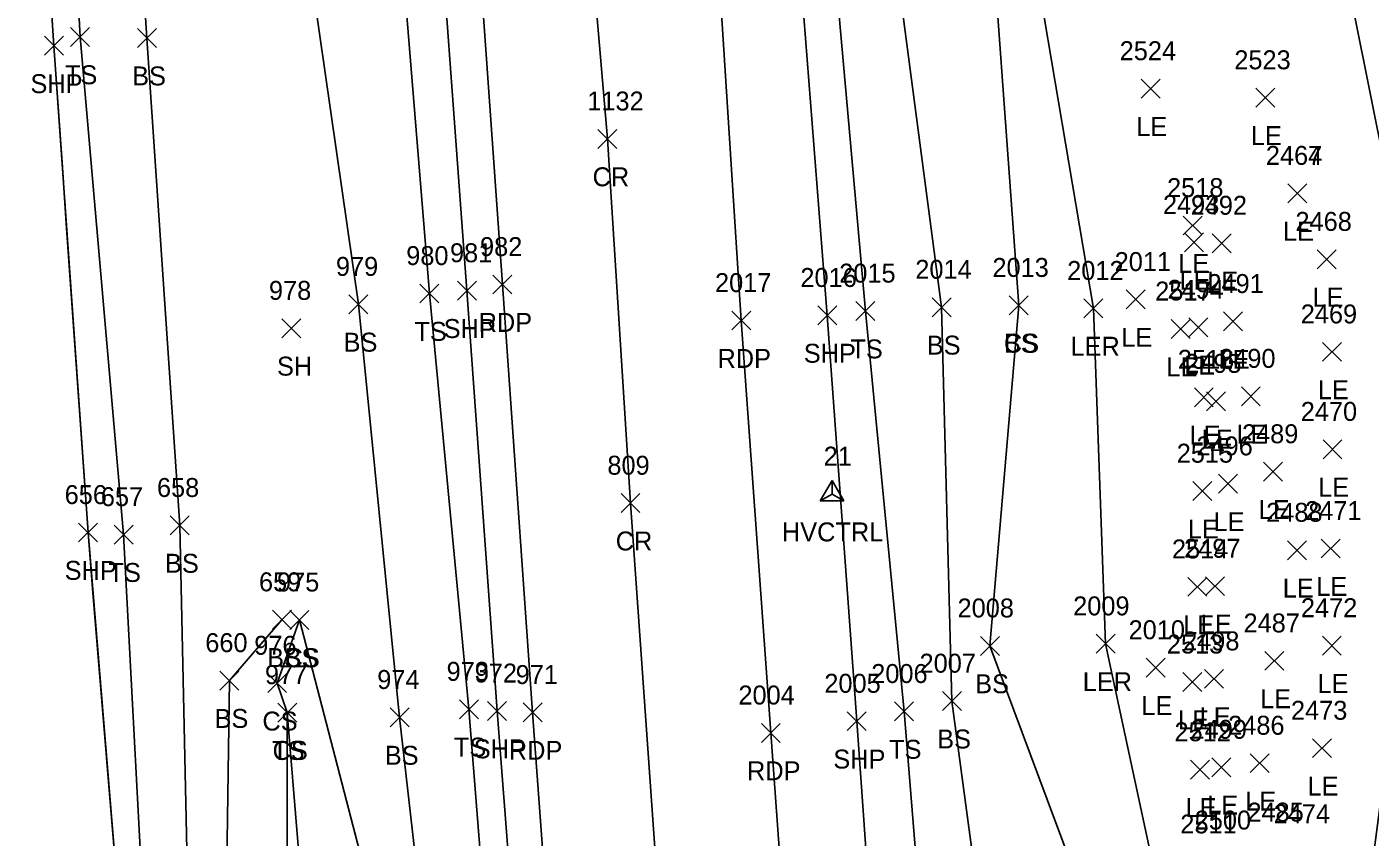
# Model space of a CAD drawing. Extents: x 1650221 to 1650634, y 244606 to 249996.
# Drawn here: x 1650345.8 to 1650487.6, y 245576.1 to 245661.6 of the extents above; entities that cross this region are included whole.
import ezdxf

# ---------------------------------------------------------------- set-up
doc = ezdxf.new("R2010")
doc.units = 0
for name, color, linetype in [('C_A', 7, 'Continuous'), ('C_I', 7, 'Continuous'), ('CPSM', 7, 'Continuous'), ('L_A', 7, 'Continuous'), ('L_I', 7, 'Continuous'), ('L_TIC', 7, 'Continuous'), ('LARO', 7, 'Continuous'), ('LELB', 7, 'Continuous'), ('LSOGP', 7, 'Continuous'), ('P_A', 7, 'Continuous'), ('P_I', 7, 'Continuous'), ('P_TIC', 7, 'Continuous'), ('PET', 7, 'Continuous'), ('PRC', 7, 'Continuous'), ('PSP', 7, 'Continuous')]:
    doc.layers.add(name, color=color, linetype=linetype)

msp = doc.modelspace()

# ---------------------------------------------------------------- linework, layer by layer
at = {"layer": 'CPSM'}
for p, q in [((1650429.52, 245611.6), (1650430.77, 245613.77)), ((1650432.02, 245611.6), (1650430.77, 245613.77)), ((1650430.77, 245612.33), (1650430.77, 245613.77)), ((1650429.52, 245611.6), (1650430.77, 245612.33)), ((1650430.77, 245612.33), (1650430.77, 245612.33)), ((1650430.77, 245612.33), (1650432.02, 245611.6)), ((1650429.52, 245611.6), (1650432.02, 245611.6))]:
    msp.add_line(p, q, dxfattribs=at)
at = {"layer": 'L_TIC'}
for points in [[(1650350.39, 245659.59), (1650352.39, 245661.59)], [(1650352.39, 245659.59), (1650350.39, 245661.59)], [(1650357.45, 245659.47), (1650359.45, 245661.47)], [(1650359.45, 245659.47), (1650357.45, 245661.47)], [(1650463.38, 245654.13), (1650465.38, 245656.13)], [(1650465.38, 245654.13), (1650463.38, 245656.13)], [(1650475.48, 245653.17), (1650477.48, 245655.17)], [(1650477.48, 245653.17), (1650475.48, 245655.17)], [(1650478.86, 245643.08), (1650480.86, 245645.08)], [(1650480.86, 245643.08), (1650478.86, 245645.08)], [(1650478.86, 245643.08), (1650480.86, 245645.08)], [(1650480.86, 245643.08), (1650478.86, 245645.08)], [(1650467.81, 245639.68), (1650469.81, 245641.68)], [(1650469.81, 245639.68), (1650467.81, 245641.68)], [(1650467.95, 245637.89), (1650469.95, 245639.89)], [(1650469.95, 245637.89), (1650467.95, 245639.89)], [(1650470.87, 245637.81), (1650472.87, 245639.81)], [(1650472.87, 245637.81), (1650470.87, 245639.81)], [(1650481.98, 245636.11), (1650483.98, 245638.11)], [(1650483.98, 245636.11), (1650481.98, 245638.11)], [(1650379.77, 245631.36), (1650381.77, 245633.36)], [(1650381.77, 245631.36), (1650379.77, 245633.36)], [(1650387.27, 245632.5), (1650389.27, 245634.5)], [(1650389.27, 245632.5), (1650387.27, 245634.5)], [(1650449.46, 245631.25), (1650451.46, 245633.25)], [(1650451.46, 245631.25), (1650449.46, 245633.25)], [(1650449.46, 245631.25), (1650451.46, 245633.25)], [(1650451.46, 245631.25), (1650449.46, 245633.25)], [(1650461.8, 245631.87), (1650463.8, 245633.87)], [(1650463.8, 245631.87), (1650461.8, 245633.87)], [(1650433.29, 245630.65), (1650435.29, 245632.65)], [(1650435.29, 245630.65), (1650433.29, 245632.65)], [(1650441.32, 245631.05), (1650443.32, 245633.05)], [(1650443.32, 245631.05), (1650441.32, 245633.05)], [(1650457.35, 245630.93), (1650459.35, 245632.93)], [(1650459.35, 245630.93), (1650457.35, 245632.93)], [(1650372.69, 245628.83), (1650374.69, 245630.83)], [(1650374.69, 245628.83), (1650372.69, 245630.83)], [(1650466.56, 245628.76), (1650468.56, 245630.76)], [(1650468.56, 245628.76), (1650466.56, 245630.76)], [(1650468.43, 245628.94), (1650470.43, 245630.94)], [(1650470.43, 245628.94), (1650468.43, 245630.94)], [(1650472.07, 245629.55), (1650474.07, 245631.55)], [(1650474.07, 245629.55), (1650472.07, 245631.55)], [(1650482.54, 245626.34), (1650484.54, 245628.34)], [(1650484.54, 245626.34), (1650482.54, 245628.34)], [(1650469, 245621.55), (1650471, 245623.55)], [(1650471, 245621.55), (1650469, 245623.55)], [(1650473.96, 245621.65), (1650475.96, 245623.65)], [(1650475.96, 245621.65), (1650473.96, 245623.65)], [(1650470.29, 245621.12), (1650472.29, 245623.12)], [(1650472.29, 245621.12), (1650470.29, 245623.12)], [(1650482.58, 245616.05), (1650484.58, 245618.05)], [(1650484.58, 245616.05), (1650482.58, 245618.05)], [(1650476.3, 245613.69), (1650478.3, 245615.69)], [(1650478.3, 245613.69), (1650476.3, 245615.69)], [(1650468.83, 245611.64), (1650470.83, 245613.64)], [(1650470.83, 245611.64), (1650468.83, 245613.64)], [(1650471.54, 245612.41), (1650473.54, 245614.41)], [(1650473.54, 245612.41), (1650471.54, 245614.41)], [(1650354.99, 245607.05), (1650356.99, 245609.05)], [(1650356.99, 245607.05), (1650354.99, 245609.05)], [(1650360.92, 245608.02), (1650362.92, 245610.02)], [(1650362.92, 245608.02), (1650360.92, 245610.02)], [(1650478.84, 245605.4), (1650480.84, 245607.4)], [(1650480.84, 245605.4), (1650478.84, 245607.4)], [(1650482.38, 245605.58), (1650484.38, 245607.58)], [(1650484.38, 245605.58), (1650482.38, 245607.58)], [(1650468.33, 245601.53), (1650470.33, 245603.53)], [(1650470.33, 245601.53), (1650468.33, 245603.53)], [(1650470.18, 245601.6), (1650472.18, 245603.6)], [(1650472.18, 245601.6), (1650470.18, 245603.6)], [(1650371.7, 245598.06), (1650373.7, 245600.06)], [(1650373.7, 245598.06), (1650371.7, 245600.06)], [(1650373.54, 245598.04), (1650375.54, 245600.04)], [(1650375.54, 245598.04), (1650373.54, 245600.04)], [(1650373.54, 245598.04), (1650375.54, 245600.04)], [(1650375.54, 245598.04), (1650373.54, 245600.04)], [(1650446.43, 245595.3), (1650448.43, 245597.3)], [(1650448.43, 245595.3), (1650446.43, 245597.3)], [(1650458.64, 245595.52), (1650460.64, 245597.52)], [(1650460.64, 245595.52), (1650458.64, 245597.52)], [(1650482.51, 245595.33), (1650484.51, 245597.33)], [(1650484.51, 245595.33), (1650482.51, 245597.33)], [(1650463.92, 245593), (1650465.92, 245595)], [(1650465.92, 245593), (1650463.92, 245595)], [(1650476.45, 245593.72), (1650478.45, 245595.72)], [(1650478.45, 245593.72), (1650476.45, 245595.72)], [(1650366.15, 245591.64), (1650368.15, 245593.64)], [(1650368.15, 245591.64), (1650366.15, 245593.64)], [(1650467.79, 245591.49), (1650469.79, 245593.49)], [(1650469.79, 245591.49), (1650467.79, 245593.49)], [(1650470.07, 245591.82), (1650472.07, 245593.82)], [(1650472.07, 245591.82), (1650470.07, 245593.82)], [(1650371.2, 245591.36), (1650373.2, 245593.36)], [(1650373.2, 245591.36), (1650371.2, 245593.36)], [(1650391.44, 245588.61), (1650393.44, 245590.61)], [(1650393.44, 245588.61), (1650391.44, 245590.61)], [(1650442.42, 245589.47), (1650444.42, 245591.47)], [(1650444.42, 245589.47), (1650442.42, 245591.47)], [(1650372.27, 245588.26), (1650374.27, 245590.26)], [(1650374.27, 245588.26), (1650372.27, 245590.26)], [(1650372.27, 245588.26), (1650374.27, 245590.26)], [(1650374.27, 245588.26), (1650372.27, 245590.26)], [(1650372.27, 245588.26), (1650374.27, 245590.26)], [(1650374.27, 245588.26), (1650372.27, 245590.26)], [(1650384.12, 245587.75), (1650386.12, 245589.75)], [(1650386.12, 245587.75), (1650384.12, 245589.75)], [(1650437.37, 245588.38), (1650439.37, 245590.38)], [(1650439.37, 245588.38), (1650437.37, 245590.38)], [(1650481.46, 245584.5), (1650483.46, 245586.5)], [(1650483.46, 245584.5), (1650481.46, 245586.5)], [(1650474.88, 245582.92), (1650476.88, 245584.92)], [(1650476.88, 245582.92), (1650474.88, 245584.92)], [(1650468.59, 245582.23), (1650470.59, 245584.23)], [(1650470.59, 245582.23), (1650468.59, 245584.23)], [(1650470.86, 245582.49), (1650472.86, 245584.49)], [(1650472.86, 245582.49), (1650470.86, 245584.49)]]:
    msp.add_lwpolyline(points, dxfattribs=at)
at = {"layer": 'LARO'}
msp.add_lwpolyline([(1650491, 245121.86), (1650493.61, 245139.73), (1650488.81, 245187.64), (1650492.44, 245198.75), (1650485.3, 245221.37), (1650479.96, 245259.68), (1650476.93, 245285.6), (1650472.44, 245315.86), (1650475.26, 245352.64), (1650477.44, 245377.75), (1650471.06, 245430.31), (1650471.03, 245462.47), (1650469.65, 245517.3), (1650470.03, 245548.03), (1650459.64, 245596.52), (1650458.35, 245631.93), (1650449.5, 245684.33)], dxfattribs=at)
at = {"layer": 'LELB'}
for points in [[(1650349.13, 245703.09), (1650351.39, 245660.59), (1650355.99, 245608.05), (1650358.47, 245560.96), (1650362.91, 245508.7), (1650365.76, 245471.06), (1650369.41, 245419.53), (1650373.04, 245367.18), (1650376.89, 245316.29), (1650379.01, 245269.77), (1650383.48, 245220.96), (1650387.1, 245168.26), (1650390.97, 245118.17), (1650394.99, 245063.19), (1650398.03, 245017.1), (1650401.94, 244967.25), (1650403.81, 244936.86), (1650407.34, 244889.23), (1650410.84, 244834.73), (1650414.52, 244785.95), (1650419.34, 244732.83), (1650422.93, 244682.99), (1650426.36, 244632.18), (1650427.51, 244611.7)], [(1650355.71, 245703.22), (1650358.45, 245660.47), (1650361.92, 245609.02), (1650362.95, 245561.76), (1650366.97, 245508.68), (1650370.97, 245471.38), (1650374.07, 245419.38), (1650376.64, 245367.03), (1650382.18, 245316.08), (1650385.68, 245270.43), (1650388.77, 245221.07), (1650390.77, 245168.69), (1650394.69, 245118), (1650401.29, 245063.19), (1650403.89, 245017.69), (1650406.99, 244966.96), (1650408.31, 244937.61), (1650413.12, 244889.16), (1650416.09, 244835.73), (1650420.51, 244786.1), (1650423.8, 244733.3), (1650426.51, 244682.57), (1650434.12, 244632.73), (1650437.01, 244612.78)], [(1650458.26, 244631.23), (1650456.79, 244671.65), (1650452.78, 244720.4), (1650448.37, 244766.08), (1650444.9, 244801.26), (1650441.62, 244837.94), (1650439.87, 244879.23), (1650437.68, 244923.9), (1650433.87, 244972.21), (1650429.49, 245017.89), (1650426.15, 245066.7), (1650422.69, 245123.12), (1650419.86, 245170.84), (1650416.52, 245219.13), (1650411.95, 245271.56), (1650407.71, 245328.35), (1650401.82, 245379.92), (1650396.45, 245433.97), (1650394.84, 245478.56), (1650392.49, 245522.5), (1650389.35, 245551.29), (1650385.12, 245588.75), (1650380.77, 245632.36), (1650373.15, 245685.41)], [(1650462.3, 244631.92), (1650459.1, 244671.43), (1650455.6, 244720.68), (1650451.8, 244765.92), (1650449.21, 244801.88), (1650446.61, 244838.72), (1650443.38, 244880.99), (1650440.04, 244922.8), (1650437.91, 244972.67), (1650433.82, 245018.12), (1650431.01, 245067.65), (1650425.84, 245123.86), (1650424.05, 245171.63), (1650419.6, 245218.92), (1650416.04, 245272.16), (1650411.76, 245328.09), (1650406.63, 245381.03), (1650402.95, 245434.27), (1650400.25, 245479.81), (1650396.41, 245522.79), (1650395.43, 245551.92), (1650392.44, 245589.61), (1650388.27, 245633.5), (1650384.04, 245685.26)], [(1650489.71, 244991.22), (1650489.69, 245009.71), (1650486.09, 245047.64), (1650483.87, 245079.25), (1650480.92, 245116.18), (1650479.42, 245140.42), (1650476.29, 245187.3), (1650474, 245221.05), (1650469.02, 245258.31), (1650465.71, 245285.05), (1650462.26, 245315.54), (1650460.48, 245356.55), (1650462.16, 245378.82), (1650455.67, 245427.55), (1650451.48, 245462.76), (1650449.79, 245512.44), (1650449.11, 245548.12), (1650443.42, 245590.47), (1650442.32, 245632.05), (1650435.43, 245684.43)], [(1650471.05, 245115.28), (1650468.74, 245140.33), (1650464.89, 245185.98), (1650463.25, 245221.34), (1650461.37, 245257.85), (1650459.32, 245284.8), (1650456.97, 245315.55), (1650454.6, 245356.59), (1650452.98, 245378.54), (1650450.43, 245426.58), (1650446.12, 245463.42), (1650443.52, 245512.09), (1650441.71, 245548.12), (1650438.37, 245589.38), (1650434.29, 245631.65), (1650429.68, 245683.37)], [(1650450.46, 245632.25), (1650446.79, 245683.08)], [(1650504.95, 245130.46), (1650502.44, 245141.72), (1650499.16, 245156.24), (1650498.93, 245181.82), (1650503.83, 245194.54), (1650500.59, 245204.36), (1650497.12, 245222.6), (1650494.12, 245240.25), (1650494.91, 245258.03), (1650492.2, 245286.73), (1650496.63, 245312.12), (1650498.98, 245327.58), (1650495.95, 245351.61), (1650501.94, 245378.34), (1650498.52, 245407), (1650497.68, 245445.99), (1650496.14, 245475.39), (1650481.11, 245501.15), (1650483.43, 245539.97), (1650491.3, 245600.05), (1650490.9, 245637.99), (1650484.15, 245671.67)], [(1650493.15, 245007.74), (1650488.13, 245047.67), (1650486.59, 245079.09), (1650485.35, 245117.44), (1650483.97, 245140), (1650485.34, 245188.31), (1650482.43, 245221.37), (1650477.25, 245258), (1650473.1, 245285.62), (1650468.47, 245315.46), (1650468.65, 245355.64), (1650472.97, 245377.88), (1650463.98, 245429.04), (1650464.45, 245462.11), (1650460.79, 245514.67), (1650465.46, 245547.92), (1650447.43, 245596.3), (1650450.46, 245632.25)], [(1650372.7, 245599.06), (1650367.15, 245592.64), (1650366.7, 245561.16), (1650370.23, 245505.43)], [(1650374.54, 245599.04), (1650372.2, 245592.36), (1650373.27, 245589.26)], [(1650417.42, 245170.71), (1650414.29, 245218.92), (1650409.59, 245271.3), (1650405.4, 245327.96), (1650399.15, 245380.06), (1650394.45, 245434.24), (1650392.17, 245479.25), (1650388.55, 245523.47), (1650387.04, 245550.93), (1650374.54, 245599.04)], [(1650411.56, 245100.31), (1650410.98, 245134.62), (1650407.62, 245167.58), (1650401.15, 245195.95), (1650400.96, 245232.6), (1650396.91, 245255.72), (1650396.39, 245280.59), (1650392.18, 245317.33), (1650390.56, 245355.55), (1650386.02, 245389.39), (1650383.37, 245430.51), (1650379.67, 245462.51), (1650379.96, 245467.43), (1650380, 245489.06), (1650377.56, 245510.96), (1650374.72, 245546.33), (1650373.24, 245560.96), (1650373.27, 245589.26)], [(1650417.99, 245100.65), (1650416.66, 245133.49), (1650414.16, 245167.69), (1650410.2, 245197), (1650406.67, 245233.63), (1650402.8, 245260.5), (1650403.69, 245281.19), (1650397.99, 245316.2), (1650398.84, 245356.67), (1650390.42, 245389.46), (1650390.16, 245432.43), (1650385.39, 245460.04), (1650384.98, 245466.18), (1650387.77, 245488.08), (1650384.3, 245517.36), (1650381.95, 245546.8), (1650375.57, 245561.13), (1650373.27, 245589.26)]]:
    msp.add_lwpolyline(points, dxfattribs=at)
at = {"layer": 'LSOGP'}
msp.add_lwpolyline([(1650348.27, 245665.09), (1650348.63, 245659.65), (1650349.08, 245653.23), (1650349.53, 245646.81), (1650349.98, 245640.39), (1650350.43, 245633.96), (1650350.88, 245627.54), (1650351.33, 245621.12), (1650351.78, 245614.7), (1650352.24, 245608.27), (1650352.72, 245602.34), (1650353.21, 245596.4), (1650353.7, 245590.46), (1650354.19, 245584.52), (1650354.68, 245578.58), (1650355.17, 245572.64)], dxfattribs=at)
at = {"layer": 'P_TIC'}
for points in [[(1650347.63, 245658.65), (1650349.63, 245660.65)], [(1650349.63, 245658.65), (1650347.63, 245660.65)], [(1650406.05, 245648.82), (1650408.05, 245650.82)], [(1650408.05, 245648.82), (1650406.05, 245650.82)], [(1650391.23, 245632.8), (1650393.23, 245634.8)], [(1650393.23, 245632.8), (1650391.23, 245634.8)], [(1650394.97, 245633.45), (1650396.97, 245635.45)], [(1650396.97, 245633.45), (1650394.97, 245635.45)], [(1650429.25, 245630.19), (1650431.25, 245632.19)], [(1650431.25, 245630.19), (1650429.25, 245632.19)], [(1650420.18, 245629.65), (1650422.18, 245631.65)], [(1650422.18, 245629.65), (1650420.18, 245631.65)], [(1650408.49, 245610.37), (1650410.49, 245612.37)], [(1650410.49, 245610.37), (1650408.49, 245612.37)], [(1650351.24, 245607.27), (1650353.24, 245609.27)], [(1650353.24, 245607.27), (1650351.24, 245609.27)], [(1650394.41, 245588.43), (1650396.41, 245590.43)], [(1650396.41, 245588.43), (1650394.41, 245590.43)], [(1650398.16, 245588.27), (1650400.16, 245590.27)], [(1650400.16, 245588.27), (1650398.16, 245590.27)], [(1650432.37, 245587.35), (1650434.37, 245589.35)], [(1650434.37, 245587.35), (1650432.37, 245589.35)], [(1650423.3, 245586.11), (1650425.3, 245588.11)], [(1650425.3, 245586.11), (1650423.3, 245588.11)]]:
    msp.add_lwpolyline(points, dxfattribs=at)
at = {"layer": 'PET'}
for points in [[(1650468.61, 244633.66), (1650465.16, 244679.18), (1650461.18, 244730.39), (1650457.78, 244777.29), (1650455.76, 244806.01), (1650453.3, 244838.79), (1650450.33, 244880.04), (1650447.22, 244922.32), (1650443.48, 244972.73), (1650440.49, 245018.18), (1650436.73, 245069.12), (1650432.63, 245123.79), (1650429.44, 245172.68), (1650426.2, 245218.76), (1650422.12, 245272.82), (1650418.28, 245328.28), (1650414.28, 245381.59), (1650410.42, 245434.18), (1650407.03, 245480.26), (1650404.25, 245522.13), (1650401.81, 245552.98), (1650399.16, 245589.27), (1650395.97, 245634.45), (1650392.36, 245685.55)], [(1650458.15, 245114.32), (1650456.62, 245139.84), (1650453.42, 245185.54), (1650451.1, 245220.97), (1650448.32, 245256.66), (1650446.89, 245283.96), (1650444.13, 245314.19), (1650440.98, 245355.92), (1650439.55, 245378.58), (1650435.64, 245425.9), (1650433.13, 245463.89), (1650429.51, 245512.19), (1650427.14, 245547.69), (1650424.3, 245587.11), (1650421.18, 245630.65), (1650417.91, 245681.78)]]:
    msp.add_lwpolyline(points, dxfattribs=at)
at = {"layer": 'PRC'}
msp.add_lwpolyline([(1650447.57, 245085.81), (1650443.28, 245144.22), (1650439.84, 245189.25), (1650436.21, 245244.62), (1650432.57, 245294.06), (1650428.87, 245344.44), (1650424.91, 245397.45), (1650422.06, 245440.46), (1650418.2, 245485.2), (1650414.81, 245534.63), (1650412.73, 245565.5), (1650409.49, 245611.37), (1650407.05, 245649.82), (1650403.01, 245697.04)], dxfattribs=at)
at = {"layer": 'PSP'}
for points in [[(1650345.78, 245703.18), (1650348.63, 245659.65), (1650352.24, 245608.27), (1650356.14, 245560.76), (1650359.83, 245508.67), (1650362.71, 245470.35), (1650366.37, 245419.55), (1650370.09, 245366.17), (1650373.73, 245316.16), (1650376.75, 245269.64), (1650380.21, 245220.67), (1650384.07, 245168.16), (1650387.54, 245117.86), (1650391.85, 245063.26), (1650394.9, 245017.42), (1650398.56, 244967.17), (1650400.8, 244936.49), (1650404.42, 244889.02), (1650408.47, 244833.97), (1650411.77, 244786.13), (1650415.79, 244732.16), (1650419.27, 244682.87), (1650423.02, 244632.43), (1650424.78, 244611.26)], [(1650464.84, 244632.07), (1650461.81, 244671.31), (1650457.94, 244720.75), (1650454.77, 244765.54), (1650451.99, 244802.46), (1650449.34, 244838.71), (1650446.5, 244879.72), (1650443.46, 244922.98), (1650439.98, 244973.19), (1650436.37, 245018.02), (1650433.26, 245068.28), (1650429.09, 245123.84), (1650425.59, 245171.99), (1650422.33, 245218.99), (1650418.38, 245272.19), (1650414.3, 245328), (1650410.4, 245381.3), (1650406.52, 245434.23), (1650403.48, 245480), (1650400.24, 245522.79), (1650398.25, 245552.46), (1650395.41, 245589.43), (1650392.23, 245633.8), (1650388.44, 245685.1)], [(1650467.35, 245115.19), (1650465.66, 245140.38), (1650462.4, 245185.76), (1650459.93, 245221.23), (1650457.1, 245257.2), (1650455.22, 245284.62), (1650453.41, 245314.94), (1650449.96, 245356.27), (1650448.46, 245377.97), (1650444.62, 245426.85), (1650442.19, 245463.43), (1650438.55, 245512.23), (1650436.23, 245548.05), (1650433.37, 245588.35), (1650430.25, 245631.19), (1650426.21, 245683.01)]]:
    msp.add_lwpolyline(points, dxfattribs=at)

# ---------------------------------------------------------------- texts
at = {"layer": 'C_A'}
msp.add_text('HVCTRL', height=2, dxfattribs=at).set_placement((1650425.47, 245607.33))
at = {"layer": 'C_I'}
msp.add_text('21', height=2, dxfattribs=at).set_placement((1650429.88, 245615.33))
at = {"layer": 'L_A'}
for s, p in [('TS', (1650349.8, 245655.59)), ('BS', (1650356.89, 245655.47)), ('LE', (1650462.87, 245650.13)), ('LE', (1650474.97, 245649.17)), ('LE', (1650478.35, 245639.08)), ('LE', (1650478.35, 245639.08)), ('LE', (1650467.3, 245635.68)), ('LE', (1650467.44, 245633.89)), ('LE', (1650470.36, 245633.81)), ('LE', (1650481.47, 245632.11)), ('TS', (1650386.68, 245628.5)), ('BS', (1650379.21, 245627.36)), ('BS', (1650440.76, 245627.05)), ('CS', (1650448.9, 245627.25)), ('BS', (1650448.9, 245627.25)), ('LER', (1650455.93, 245626.93)), ('LE', (1650461.29, 245627.87)), ('TS', (1650432.7, 245626.65)), ('LE', (1650471.56, 245625.55)), ('SH', (1650372.18, 245624.83)), ('LE', (1650466.05, 245624.76)), ('LE', (1650467.92, 245624.94)), ('LE', (1650482.03, 245622.34)), ('LE', (1650468.49, 245617.55)), ('LE', (1650469.78, 245617.12)), ('LE', (1650473.45, 245617.65)), ('LE', (1650482.07, 245612.05)), ('LE', (1650475.79, 245609.69)), ('LE', (1650468.32, 245607.64)), ('LE', (1650471.03, 245608.41)), ('TS', (1650354.4, 245603.05)), ('BS', (1650360.36, 245604.02)), ('LE', (1650478.33, 245601.4)), ('LE', (1650481.87, 245601.58)), ('LE', (1650467.82, 245597.53)), ('LE', (1650469.67, 245597.6)), ('BS', (1650371.14, 245594.06)), ('CS', (1650372.98, 245594.04)), ('BS', (1650372.98, 245594.04)), ('LER', (1650457.22, 245591.52)), ('BS', (1650445.87, 245591.3)), ('LE', (1650482, 245591.33)), ('LE', (1650463.41, 245589)), ('LE', (1650475.94, 245589.72)), ('BS', (1650365.59, 245587.64)), ('CS', (1650370.64, 245587.36)), ('LE', (1650467.28, 245587.49)), ('LE', (1650469.56, 245587.82)), ('TS', (1650390.85, 245584.61)), ('TS', (1650436.78, 245584.38)), ('BS', (1650441.86, 245585.47)), ('TS', (1650371.68, 245584.26)), ('TS', (1650371.68, 245584.26)), ('CS', (1650371.71, 245584.26)), ('BS', (1650383.56, 245583.75)), ('LE', (1650480.95, 245580.5)), ('LE', (1650474.37, 245578.92)), ('LE', (1650468.08, 245578.23)), ('LE', (1650470.35, 245578.49))]:
    msp.add_text(s, height=2, dxfattribs=at).set_placement(p)
at = {"layer": 'L_I'}
for s, p in [('2524', (1650461.12, 245658.13)), ('2523', (1650473.22, 245657.17)), ('2464', (1650476.55, 245647.08)), ('2467', (1650476.55, 245647.08)), ('2518', (1650466.12, 245643.68)), ('2493', (1650465.69, 245641.89)), ('2492', (1650468.61, 245641.81)), ('2468', (1650479.67, 245640.11)), ('979', (1650378.4, 245635.36)), ('980', (1650385.82, 245636.5)), ('2011', (1650460.59, 245635.87)), ('2015', (1650431.52, 245634.65)), ('2014', (1650439.55, 245635.05)), ('2013', (1650447.69, 245635.25)), ('2013', (1650447.69, 245635.25)), ('2012', (1650455.58, 245634.93)), ('978', (1650371.33, 245632.83)), ('2517', (1650464.87, 245632.76)), ('2494', (1650466.17, 245632.94)), ('2491', (1650470.38, 245633.55)), ('2469', (1650480.23, 245630.34)), ('2516', (1650467.26, 245625.55)), ('2490', (1650471.62, 245625.65)), ('2495', (1650468.03, 245625.12)), ('2470', (1650480.23, 245620.05)), ('2489', (1650474.03, 245617.69)), ('2515', (1650467.14, 245615.64)), ('2496', (1650469.22, 245616.41)), ('658', (1650359.51, 245612.02)), ('657', (1650353.59, 245611.05)), ('2488', (1650476.58, 245609.4)), ('2471', (1650480.69, 245609.58)), ('2497', (1650467.92, 245605.6)), ('2514', (1650466.64, 245605.53)), ('659', (1650370.28, 245602.06)), ('975', (1650372.18, 245602.04)), ('975', (1650372.18, 245602.04)), ('2008', (1650444.01, 245599.3)), ('2009', (1650456.21, 245599.52)), ('2472', (1650480.25, 245599.33)), ('2487', (1650474.19, 245597.72)), ('660', (1650364.61, 245595.64)), ('2010', (1650462.06, 245597)), ('2498', (1650467.81, 245595.82)), ('976', (1650369.78, 245595.36)), ('2513', (1650466.1, 245595.49)), ('2007', (1650440, 245593.47)), ('977', (1650370.91, 245592.26)), ('977', (1650370.91, 245592.26)), ('977', (1650370.91, 245592.26)), ('974', (1650382.76, 245591.75)), ('973', (1650390.08, 245592.61)), ('2006', (1650434.9, 245592.38)), ('2473', (1650479.2, 245588.5)), ('2512', (1650466.9, 245586.23)), ('2499', (1650468.6, 245586.49)), ('2486', (1650472.57, 245586.92)), ('2485', (1650474.6, 245577.75)), ('2474', (1650477.37, 245577.58)), ('2511', (1650467.52, 245576.5)), ('2500', (1650469.04, 245576.91))]:
    msp.add_text(s, height=2, dxfattribs=at).set_placement(p)
at = {"layer": 'P_A'}
for s, p in [('SHP', (1650346.16, 245654.65)), ('CR', (1650405.49, 245644.82)), ('SHP', (1650389.77, 245628.8)), ('RDP', (1650393.46, 245629.45)), ('RDP', (1650418.67, 245625.65)), ('SHP', (1650427.78, 245626.19)), ('CR', (1650407.93, 245606.37)), ('SHP', (1650349.77, 245603.27)), ('SHP', (1650392.95, 245584.43)), ('RDP', (1650396.65, 245584.27)), ('SHP', (1650430.9, 245583.35)), ('RDP', (1650421.79, 245582.11))]:
    msp.add_text(s, height=2, dxfattribs=at).set_placement(p)
at = {"layer": 'P_I'}
for s, p in [('1132', (1650404.93, 245652.82)), ('981', (1650390.44, 245636.8)), ('982', (1650393.61, 245637.45)), ('2016', (1650427.42, 245634.19)), ('2017', (1650418.41, 245633.65)), ('809', (1650407.05, 245614.37)), ('656', (1650349.77, 245611.27)), ('972', (1650393.05, 245592.43)), ('971', (1650397.37, 245592.27)), ('2004', (1650420.88, 245590.11)), ('2005', (1650429.95, 245591.35))]:
    msp.add_text(s, height=2, dxfattribs=at).set_placement(p)

doc.saveas('drawing.dxf')
